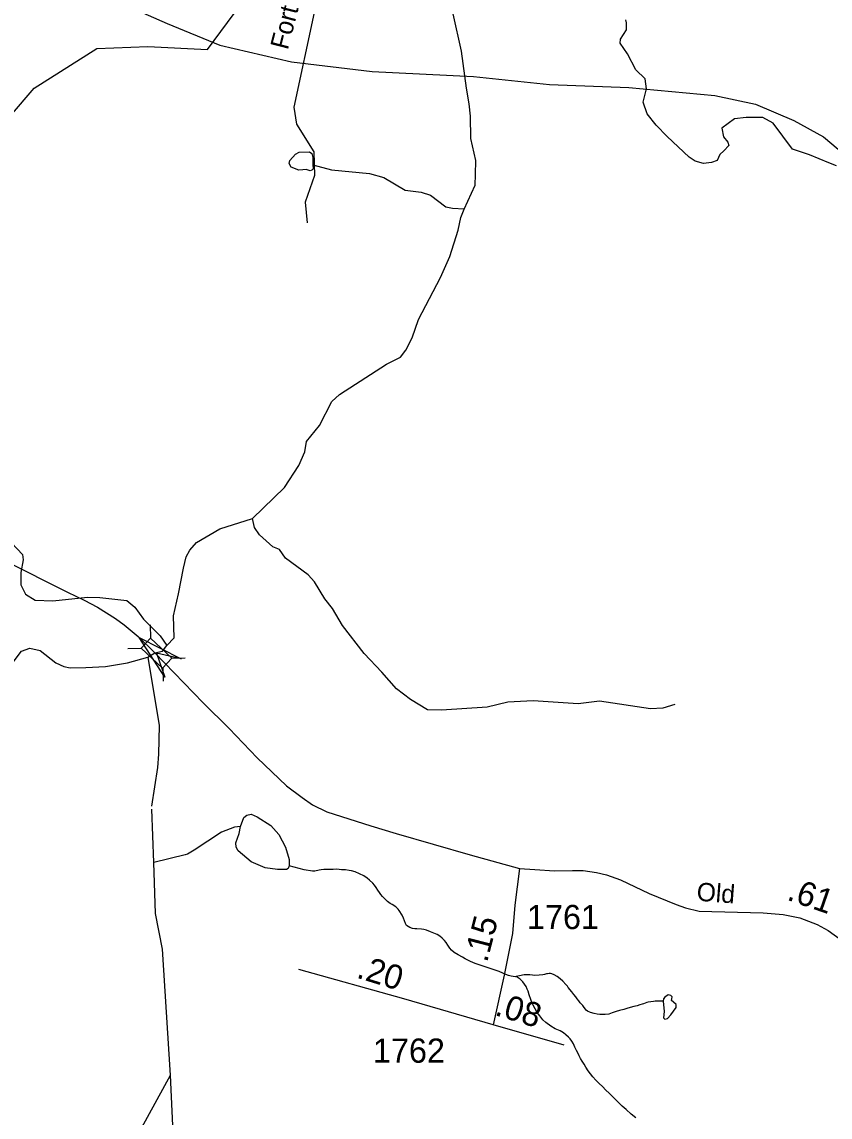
# Model space of a CAD drawing. Extents: x 2056842 to 2160602, y 826753 to 1016856.
# Drawn here: x 2129283 to 2133459, y 863143 to 868802 of the extents above; entities that cross this region are included whole.
import ezdxf

# ---------------------------------------------------------------- set-up
doc = ezdxf.new("R2010")
doc.units = 0
for name, color, linetype in [('Exist Hydrographic Creek Single Shore', 7, 'Continuous'), ('Exist Hydrographic Misc Water Feature', 7, 'Continuous'), ('Exist Road Non-System Type 51', 7, 'Continuous'), ('Exist Road Non-System Type 51 Label', 7, 'Continuous'), ('Exist Road Primary NC Attributed', 7, 'Continuous'), ('Exist Road Secondary Mileage Hundredths English Label', 7, 'Continuous'), ('Exist Road Secondary Structure Standard Bridge Attributed CELL', 7, 'Continuous'), ('Exist Road Secondary Structure Standard Bridge CELL', 7, 'Continuous'), ('Exist Road Secondary Type 51 Attributed', 7, 'Continuous'), ('Exist Road Secondary Type 51 Label', 7, 'Continuous'), ('Exist Road Secondary Type 51 Number Label', 7, 'Continuous')]:
    doc.layers.add(name, color=color, linetype=linetype)

msp = doc.modelspace()

# ---------------------------------------------------------------- linework, layer by layer
at = {"layer": 'Exist Hydrographic Creek Single Shore'}
for points in [[(2131568, 867835.4), (2131625.6, 867959.3), (2131626.9, 868013.3), (2131629.4, 868086.2), (2131602.4, 868199.6), (2131600.5, 868315.6), (2131594.2, 868378.4), (2131581.3, 868459.5), (2131554.4, 868651.4), (2131511.5, 868844.8), (2131388.4, 869126.3), (2131319.2, 869279.5), (2131309.2, 869367.4), (2131331.8, 869457.9), (2131383.3, 869550.9), (2131448.6, 869628.8), (2131486, 869644.6)], [(2130475.2, 866236.9), (2130640.6, 866395.6), (2130714, 866509.6), (2130745.4, 866581.3), (2130754.2, 866634), (2130821.1, 866716.4), (2130884.8, 866840.8), (2130923.7, 866877.3), (2131167.3, 867033.1), (2131240.1, 867069.5), (2131266.5, 867105.9), (2131299.2, 867170), (2131333.1, 867264.2), (2131446.1, 867482.1), (2131493.8, 867590.1), (2131537.7, 867725.8), (2131550.4, 867791.2), (2131568, 867835.4)], [(2130032.2, 865579.9), (2130069.8, 865620.1), (2130066.1, 865733.9), (2130092.5, 865847), (2130118.5, 865979.2), (2130132.2, 866037.3), (2130150, 866073.4), (2130185.9, 866111.7), (2130305.5, 866182.1), (2130475.2, 866236.9)], [(2128736.5, 864739.6), (2128759.9, 864837.7), (2128799.7, 864891.8), (2128819.8, 864902), (2128871.4, 864954.2), (2128913.3, 865024.4), (2129010.7, 865120.8), (2129050.4, 865181), (2129098, 865287.1), (2129227, 865479.7), (2129280.7, 865549.9), (2129324.6, 865566.1), (2129376.7, 865554.4), (2129458.9, 865490.7), (2129498.9, 865470.9), (2129532.9, 865465), (2129612.9, 865465.4), (2129715.7, 865471.9), (2129829, 865489.5), (2129933, 865519.2)], [(2129933, 865519.2), (2129970.1, 865541.9), (2130008.7, 865550.3), (2130032.2, 865579.9)], [(2129933, 865519.2), (2129992.1, 865166.9), (2129988.7, 865019), (2129982.9, 864950.3), (2129952.7, 864750)], [(2130064.1, 863061.9), (2130051.5, 863360.1), (2130010.1, 864010.9), (2129973.7, 864195.6), (2129964.9, 864459.4), (2129954.7, 864733.9)]]:
    msp.add_lwpolyline(points, dxfattribs=at)
at = {"layer": 'Exist Hydrographic Misc Water Feature'}
for points in [[(2132511.1, 868455.7), (2132502.9, 868507.6), (2132454.9, 868555.3), (2132412.5, 868637.1), (2132374.1, 868693), (2132376.2, 868713), (2132408, 868761.1), (2132407.8, 868797.1), (2132403.7, 868813.1)], [(2133492.9, 868058.1), (2133452.7, 868073.8), (2133353.4, 868115.6), (2133264.3, 868144.5), (2133165.1, 868278.9), (2133112.3, 868307.8), (2133025.7, 868307.8), (2132965.4, 868301.5), (2132900.1, 868253.8), (2132907.7, 868208.5), (2132930.3, 868180.9), (2132936.6, 868163.3), (2132910.2, 868136.9), (2132888.8, 868116.8), (2132876.3, 868086.7), (2132847.4, 868075.4), (2132804.7, 868070.3), (2132762, 868082.9), (2132730.6, 868103), (2132617.6, 868209.8), (2132560.1, 868267.9), (2132514, 868327.7), (2132493.7, 868387.6), (2132511.1, 868455.7)], [(2130785.6, 868063.6), (2130788.1, 868043.5), (2130781.8, 868035.9), (2130771.8, 868033.4), (2130751.7, 868039.7), (2130734.1, 868037.2), (2130714, 868035.9), (2130673.8, 868052.2), (2130663.8, 868071.1), (2130667.6, 868086.2), (2130696.4, 868118.8), (2130716.5, 868128.9), (2130769.3, 868131.4), (2130780.6, 868122.6), (2130785.6, 868102.5), (2130785.6, 868063.6)], [(2130785.6, 868063.6), (2130882.3, 868037.2), (2131079.4, 868019.4), (2131153.7, 867997.7), (2131264, 867932.2), (2131346, 867922.6), (2131394, 867906.8), (2131474.2, 867847.2), (2131508.2, 867839.4), (2131568.1, 867835.6)], [(2129127.3, 866299.1), (2129157.5, 866277.2), (2129189.7, 866243.3), (2129194, 866159.4), (2129202.2, 866139.5), (2129286.5, 866049.8), (2129288.7, 866021.8), (2129277, 865957.8), (2129277.2, 865893.8), (2129301.4, 865846), (2129351.5, 865814.2), (2129443.5, 865810.6), (2129621.5, 865829.3), (2129685.5, 865827.6), (2129825.3, 865812.2), (2129865.7, 865778.5), (2129911.9, 865716.7), (2129998.3, 865630.2), (2130032.2, 865579.9)], [(2132657.1, 865274.9), (2132595.4, 865256.6), (2132531.4, 865252.3), (2132267.1, 865293.1), (2132157.4, 865278.7), (2131925.5, 865293.6), (2131793.4, 865287.1), (2131687.4, 865260.6), (2131451.6, 865245.6), (2131379.6, 865247.2), (2131291.5, 865300.8), (2131219.1, 865356.5), (2131143, 865442.2), (2131052.4, 865537.8), (2130939.6, 865683.2), (2130887.5, 865771), (2130849.2, 865820.8), (2130794.8, 865908.5), (2130762.6, 865944.4), (2130644.5, 866031.8), (2130614.2, 866075.7), (2130580.1, 866089.6), (2130510, 866151.2), (2130485.6, 866189.1), (2130475.4, 866237)], [(2130413.1, 864644.1), (2130429.5, 864691.9), (2130445.8, 864703.2), (2130467.1, 864708.2), (2130498.5, 864694.4), (2130570.1, 864649.1), (2130610.3, 864602.7), (2130645.4, 864538.6), (2130664.3, 864474.5), (2130664.3, 864440.6)], [(2130413.1, 864644.1), (2130382.3, 864640.9), (2130314, 864616.1), (2130172.7, 864523.1), (2130139.3, 864502.4), (2130127.2, 864498.6), (2129964.9, 864459.4)], [(2130664.3, 864440.6), (2130659.3, 864428), (2130650.5, 864423), (2130604, 864421.7), (2130540, 864431.8), (2130468.4, 864461.9), (2130400.6, 864519.7), (2130390.5, 864538.6), (2130389.3, 864559.9), (2130405.6, 864607.7), (2130413.1, 864644.1)], [(2131837.5, 863870.2), (2131831.6, 863868.6), (2131821.7, 863868.8), (2131810.5, 863870.7), (2131797.9, 863874.3), (2131783.6, 863879.5), (2131767.6, 863886.4), (2131749.1, 863895), (2131728, 863902.8), (2131703.4, 863911.5), (2131671.4, 863921.1), (2131651.3, 863927.4), (2131625.1, 863936.9), (2131601.1, 863947.3), (2131573.2, 863960.9), (2131559.3, 863968.6), (2131536.9, 863982.1), (2131517, 863994.1), (2131502.9, 864005.8), (2131494.5, 864015.9), (2131484.6, 864031.7), (2131476, 864045), (2131466.4, 864055.9), (2131454.1, 864067.5), (2131442.2, 864077.7), (2131428.2, 864086.2), (2131411.8, 864093.1), (2131394, 864100.8), (2131373.9, 864108.7), (2131360, 864113), (2131347.9, 864114.8), (2131323.9, 864116.2), (2131314, 864116.4), (2131301.7, 864118.3), (2131288, 864121.9), (2131278.8, 864127), (2131271.2, 864133.7), (2131265.6, 864143.6), (2131260.7, 864156.8), (2131255.4, 864170.1), (2131247.4, 864185.9), (2131233.2, 864209.9), (2131226.9, 864217.4), (2131218.9, 864225.8), (2131215, 864229.1), (2131196.9, 864241), (2131186.7, 864247), (2131172.1, 864257.9), (2131157.4, 864273), (2131147.1, 864283), (2131138.1, 864293.9), (2131130.9, 864303.9), (2131122.1, 864316.4), (2131113.9, 864328.9), (2131105.9, 864340.6), (2131095.8, 864352.3), (2131079.6, 864368.1), (2131067.8, 864378.2), (2131049.7, 864390.1), (2131027.4, 864400.3), (2131005.4, 864409.9), (2130985.5, 864416), (2130973.4, 864417.9), (2130955, 864419.9), (2130935.1, 864421.2), (2130922.2, 864422.2), (2130907.4, 864423.3), (2130891.4, 864422.9), (2130879.1, 864423.1), (2130862.1, 864422.7), (2130843.4, 864422.2), (2130830.1, 864420.8), (2130819.4, 864418.6), (2130797.5, 864414.2), (2130783.8, 864413.6), (2130740.9, 864420.5), (2130664.3, 864440.6)], [(2132596.8, 863742), (2132554.6, 863741.4), (2132546.6, 863740.7), (2132532.6, 863738.5), (2132518.7, 863736.4), (2132512.8, 863734.8), (2132494.7, 863728.6), (2132488.8, 863726.3), (2132476.7, 863722.4), (2132462.1, 863718.6), (2132444.9, 863714), (2132426.8, 863709.5), (2132409.2, 863704.2), (2132393, 863699.6), (2132371.9, 863694.2), (2132353.2, 863688.9), (2132333.1, 863681.1), (2132315.5, 863675), (2132297.4, 863672.9), (2132283.5, 863672.3), (2132269.8, 863672.6), (2132255.2, 863674.6), (2132239.4, 863678.1), (2132221.4, 863683.5), (2132205.2, 863690.3), (2132198.4, 863696.3), (2132193.1, 863702), (2132184.9, 863713.7), (2132181, 863719.6), (2132168.7, 863733.7), (2132160.7, 863744.6), (2132151.7, 863753.8), (2132144.7, 863763.8), (2132134.4, 863777.1), (2132124.4, 863789.6), (2132106.1, 863813), (2132101.8, 863818.8), (2132093.8, 863828.8), (2132078.5, 863844.6), (2132063.9, 863858.1), (2132048.9, 863869.2), (2132033.8, 863878.4), (2132022.3, 863882.8), (2132013.7, 863884.6), (2132006.9, 863884.7), (2131999.7, 863884), (2131993.8, 863882.6), (2131983.7, 863880.3), (2131975.7, 863878), (2131955.6, 863875.9), (2131933.7, 863875.5), (2131921.6, 863875.8), (2131907.6, 863877.8), (2131893.7, 863878.9), (2131877.7, 863877.6), (2131853.9, 863873.1), (2131837.5, 863870.2)], [(2132456.2, 863139.7), (2132432, 863158.2), (2132405.7, 863181.7), (2132385.4, 863199.3), (2132363.5, 863219.5), (2132343.2, 863241.3), (2132331.1, 863253), (2132316.9, 863267.2), (2132300.7, 863282.4), (2132282.7, 863300.7), (2132266.7, 863316.6), (2132248.2, 863334.3), (2132234.1, 863350.2), (2132221, 863366.1), (2132209.9, 863381.8), (2132197.6, 863400.1), (2132187.7, 863415.9), (2132177.5, 863431.8), (2132169.5, 863445.8), (2132163.3, 863460), (2132155.1, 863475.7), (2132149.2, 863487.2), (2132141, 863503.9), (2132132.6, 863521.3), (2132124.6, 863535.3), (2132116.4, 863547), (2132108.4, 863555.3), (2132094.4, 863568.7), (2132082.4, 863578.9), (2132064.1, 863589), (2132038.5, 863598.6), (2132015.9, 863612.2), (2131989.9, 863632.4), (2131975.7, 863645.8), (2131959.7, 863665.8), (2131945.4, 863683.4), (2131935.1, 863701.6), (2131925.1, 863721.5), (2131918.9, 863734.8), (2131913, 863751.3), (2131904.6, 863775.3), (2131898.4, 863793.5), (2131894.3, 863803.3), (2131888.4, 863817.4), (2131881, 863829.9), (2131872, 863841.6), (2131857.8, 863855), (2131837.5, 863870.2)], [(2132596.8, 863742), (2132601.8, 863689.2), (2132599.3, 863656.6), (2132605.6, 863649), (2132619.4, 863652.8), (2132635.7, 863671.6), (2132663.3, 863709.3), (2132664.6, 863724.4), (2132650.8, 863737), (2132639.5, 863745.8), (2132640.7, 863754.6), (2132643.2, 863764.6), (2132637, 863770.9), (2132621.9, 863774.7), (2132605.6, 863763.4), (2132599.3, 863754.6), (2132596.8, 863742)], [(2129421.5, 862863.7), (2129478.6, 862906.3), (2129501.7, 862926.9), (2129515.1, 862935.4), (2129552.7, 862948.8), (2129615.9, 862952.5), (2129719.3, 862954.9), (2129758.2, 862957.3), (2129816.7, 862998.2), (2129903.3, 863088.7), (2130051.5, 863360.1)]]:
    msp.add_lwpolyline(points, dxfattribs=at)
at = {"layer": 'Exist Road Non-System Type 51'}
for points in [[(2130786, 869459.1), (2130874.2, 869415), (2130898.7, 869341.5), (2130688.1, 868361.4), (2130702.8, 868273.2), (2130790.9, 868131.1), (2130795.8, 868008.5), (2130746.8, 867871.3), (2130756.6, 867763.5)], [(2129005.1, 867873.7), (2129023.1, 868057.6), (2129145.5, 868175.2), (2129223.9, 868317.3), (2129346.3, 868459.4), (2129669.5, 868665.2), (2129933.9, 868675), (2130242.4, 868660.3), (2130379.6, 868846.5)]]:
    msp.add_lwpolyline(points, dxfattribs=at)
at = {"layer": 'Exist Road Primary NC Attributed'}
msp.add_lwpolyline([(2129334, 869102.7), (2130034.2, 868793.7), (2130305.9, 868681.5), (2130676.4, 868595.9), (2131093.5, 868545.5), (2131616.1, 868520.8), (2132009.4, 868479), (2132418.9, 868462.8), (2132863.5, 868422.9), (2133074.5, 868377.3), (2133272.1, 868293.6), (2133425.1, 868209), (2133632.2, 868034), (2134012.2, 867655.7), (2134661.1, 867025.3), (2134908.1, 866823.8), (2135085.8, 866691.6), (2135334.7, 866560.4), (2135730, 866429.2), (2136375.1, 866279.9), (2136709.5, 866179.2), (2137090.5, 866048.9), (2137360.3, 865917.7)], dxfattribs=at)
at = {"layer": 'Exist Road Secondary Structure Standard Bridge Attributed CELL'}
msp.add_lwpolyline([(2130021.4, 865416.7), (2129888.2, 865620.9), (2130105.7, 865510.6), (2129978.9, 865539.5)], close=True, dxfattribs=at)
at = {"layer": 'Exist Road Secondary Structure Standard Bridge CELL'}
for p, q in [((2129945.5, 865687), (2129947.8, 865618.1)), ((2129830.6, 865564.3), (2129899.6, 865566.5)), ((2130057.9, 865514.6), (2130126.9, 865516.8)), ((2130010.8, 865464.2), (2130013, 865395.2))]:
    msp.add_line(p, q, dxfattribs=at)
msp.add_lwpolyline([(2129947.8, 865618.1), (2130058.1, 865514.8), (2130009.9, 865463.3), (2129899.6, 865566.5)], close=True, dxfattribs=at)
at = {"layer": 'Exist Road Secondary Type 51 Attributed'}
for points in [[(2129203, 866013.3), (2129310.5, 865959.9), (2129402.3, 865914), (2129518.3, 865855.7), (2129604.6, 865814.9), (2129674.1, 865778.7), (2129765.9, 865719.5), (2129811.2, 865687.1), (2129884.3, 865626.7), (2129970.1, 865541.9)], [(2129970.1, 865541.9), (2130218.9, 865284.2), (2130354.2, 865150.4), (2130499.2, 865000.3), (2130650.2, 864854.8), (2130731.1, 864795), (2130784.3, 864756.3), (2130859.2, 864720.1), (2131086.9, 864647.3), (2131216.8, 864609.2), (2131599.7, 864499), (2131854.6, 864428.3)], [(2131854.6, 864428.3), (2131831.1, 864238.3), (2131817.8, 864092.2), (2131774.3, 863876.5), (2131718.7, 863620.4)], [(2131854.6, 864428.3), (2131934.3, 864422.3), (2132035.2, 864414.7), (2132128.2, 864417.7), (2132183.8, 864417.7), (2132251.5, 864406.9), (2132303.4, 864394.8), (2132377.1, 864368.2), (2132524.5, 864298.1), (2132664.6, 864240.8), (2132712.9, 864223.8), (2132783, 864206.9), (2133112.8, 864197.9), (2133216.7, 864189.4), (2133302.5, 864173.1), (2133393.1, 864138.1), (2133448.6, 864106.7), (2133554.9, 864031.8), (2133668.5, 863949), (2134312.3, 863453.9), (2134533.7, 863297), (2134688.1, 863187.3)], [(2131718.7, 863620.4), (2131256, 863753.3), (2130714.8, 863905.5)], [(2132086, 863515.3), (2131718.7, 863620.4)]]:
    msp.add_lwpolyline(points, dxfattribs=at)

# ---------------------------------------------------------------- texts
at = {"layer": 'Exist Road Non-System Type 51 Label'}
msp.add_text('Fort', height=95, rotation=75.5692, dxfattribs=at).set_placement((2130656.9, 868654.1))
at = {"layer": 'Exist Road Secondary Mileage Hundredths English Label'}
for s, rotation, p in [('.61', 340.8398, (2133231.3, 864267.2)), ('.15', 75.5225, (2131686.4, 863938)), ('.20', 342.8202, (2131007.1, 863864.7)), ('.08', 342.9296, (2131721.6, 863671.2))]:
    msp.add_text(s, height=125, rotation=rotation, dxfattribs=at).set_placement(p)
at = {"layer": 'Exist Road Secondary Type 51 Label'}
msp.add_text('Old', height=95, rotation=355.7244, dxfattribs=at).set_placement((2132767.4, 864261.5))
at = {"layer": 'Exist Road Secondary Type 51 Number Label'}
for s, p in [('1761', (2131893.2, 864114.5)), ('1762', (2131097.1, 863424))]:
    msp.add_text(s, height=125, dxfattribs=at).set_placement(p)

doc.saveas('drawing.dxf')
